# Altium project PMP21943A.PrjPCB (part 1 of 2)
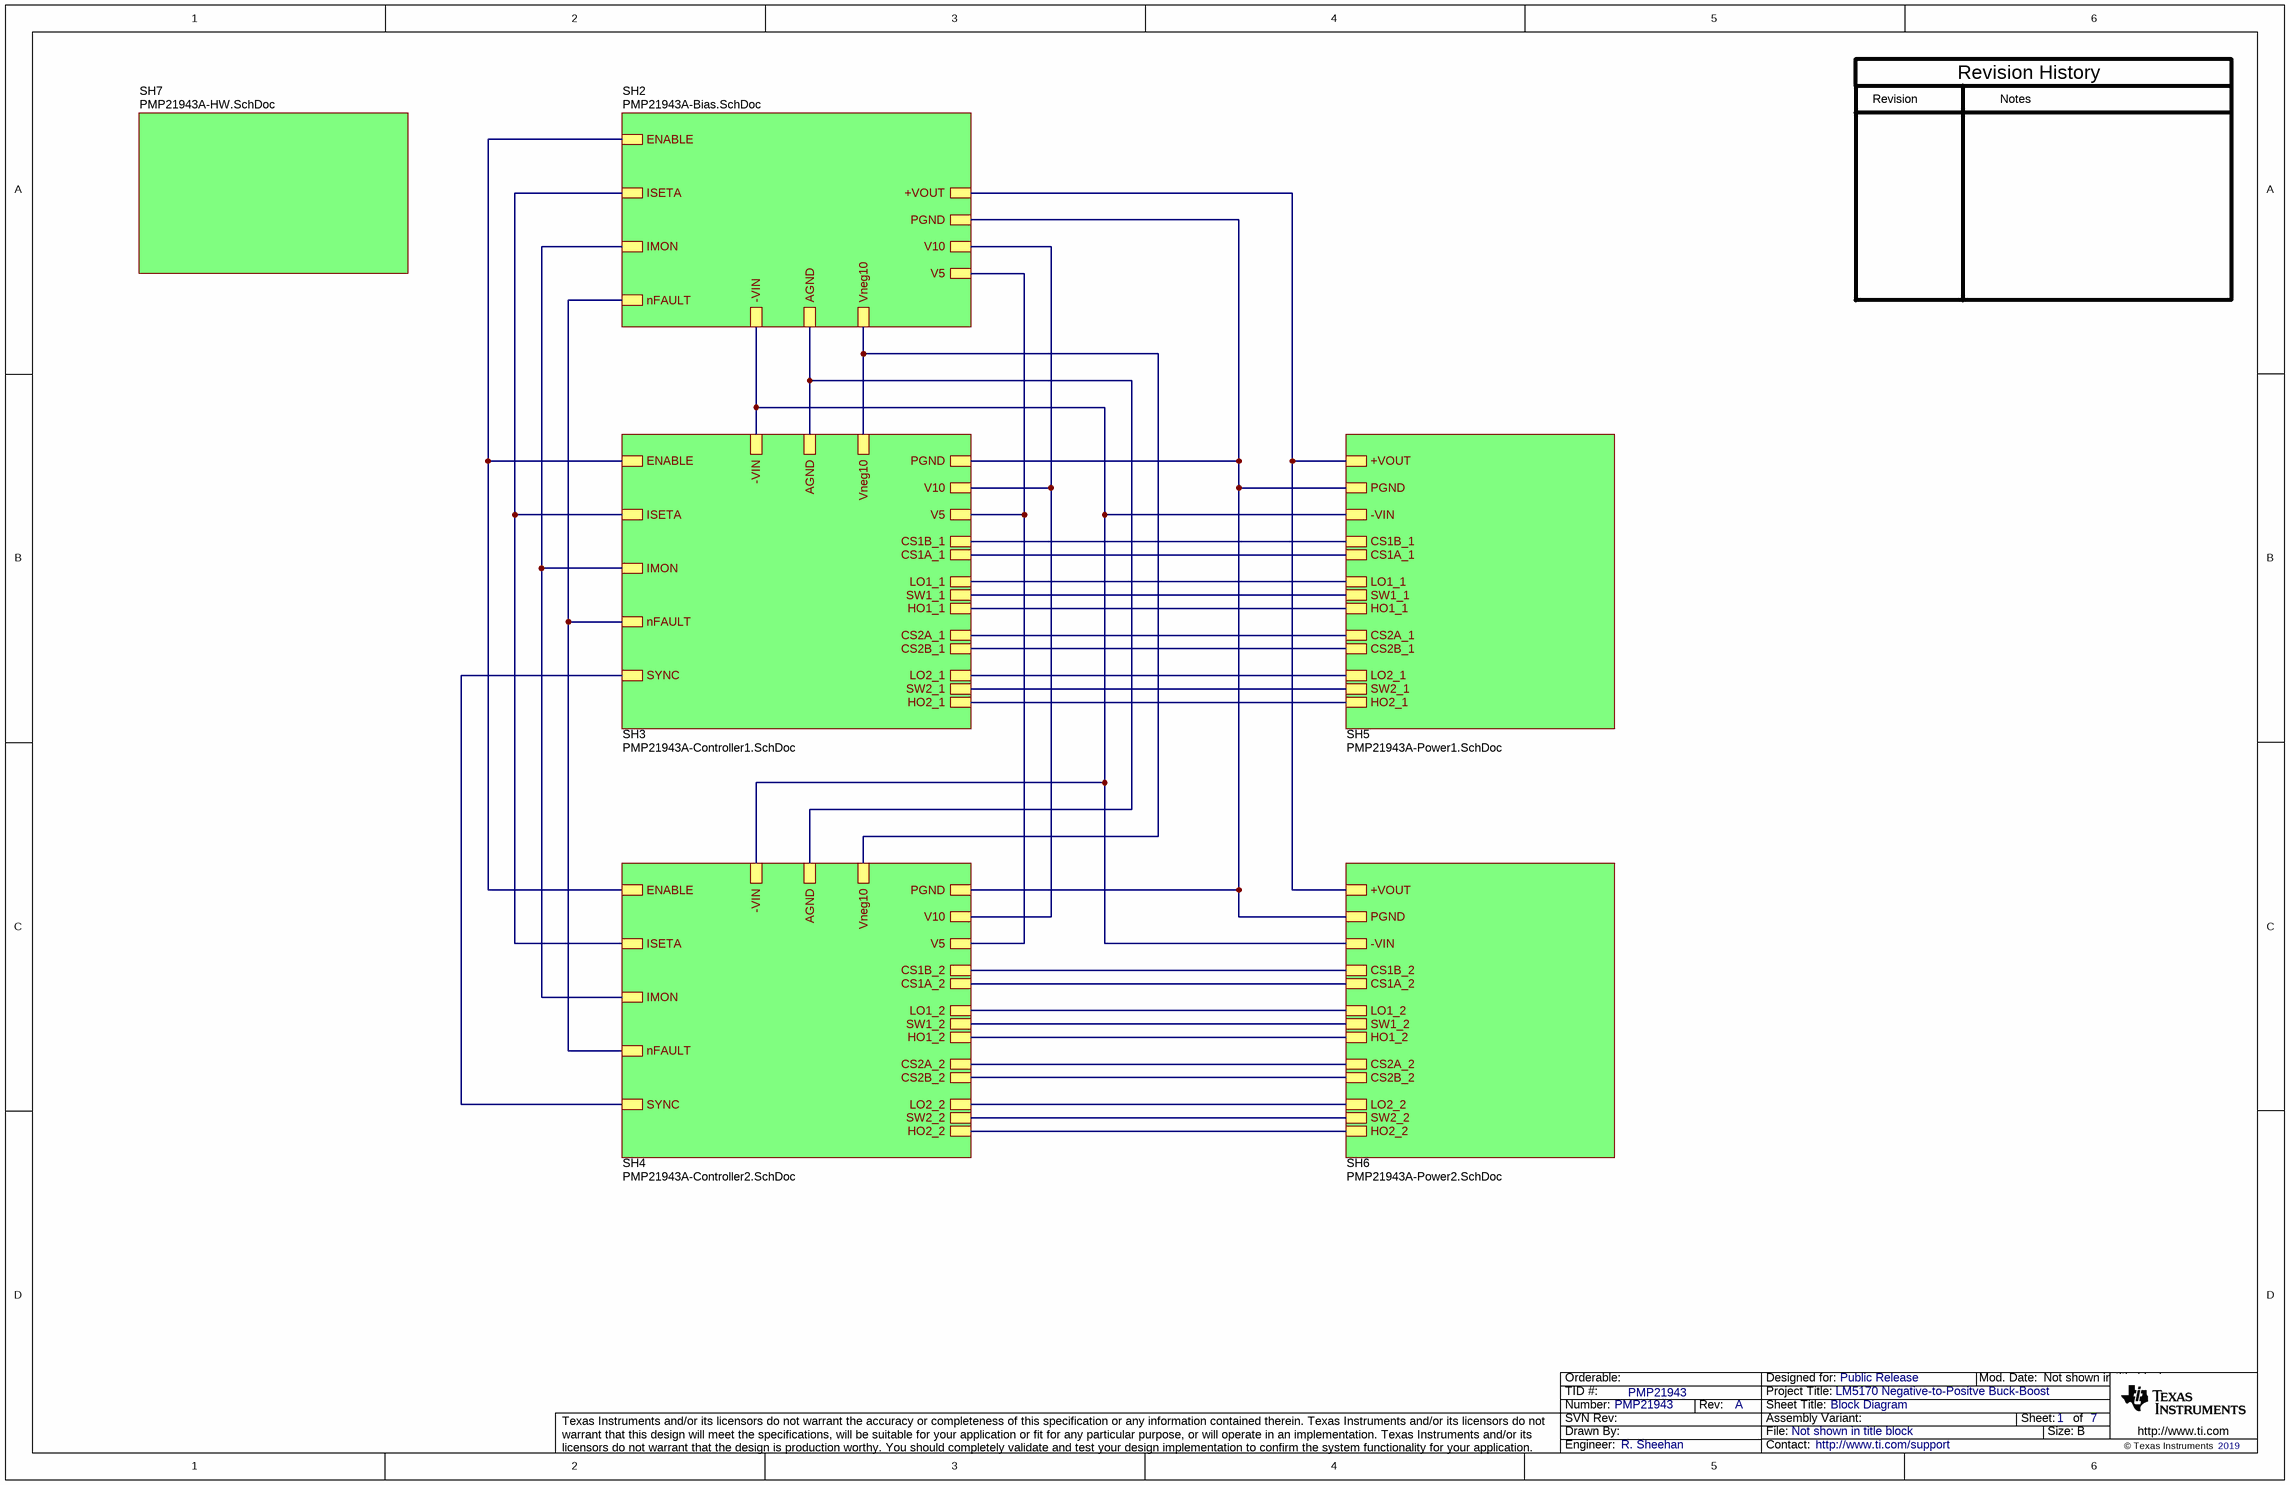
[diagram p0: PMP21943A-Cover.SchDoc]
CopyrightYear: 2019; PCB_Layout: R. Sheehan; PCB_Rev: A; PRJ_Customer: Public Release; PRJ_Engineer: R. Sheehan; PRJ_Number: PMP21943; PRJ_Title: LM5170 Negative-to-Positve Buck-Boost; SCH_Rev: A; TechSupport: http://www.ti.com/support; TID: PMP21943
7 sheets, 368 parts. Net scope: hierarchical (ports join the sheet entries above them; power ports are global).
Board file: PMP21943A.PcbDoc
Sheets:
  PMP21943A-Cover.SchDoc
    SH3 = PMP21943A-Controller1.SchDoc
    SH5 = PMP21943A-Power1.SchDoc
    SH7 = PMP21943A-HW.SchDoc
    SH2 = PMP21943A-Bias.SchDoc
    SH4 = PMP21943A-Controller2.SchDoc
    SH6 = PMP21943A-Power2.SchDoc

## Sheet PMP21943A-Cover.SchDoc: Block Diagram
size 431 x 279 mm; Date: Not shown in title block; ApprovedBy: Not shown in title block; CheckedBy: Not shown in title block; Author: Not shown in title block; CompanyName: Not shown in title block; Engineer: Not shown in title block; Organization: Not shown in title block; Address1: Not shown in title block; Address2: Not shown in title block; Address3: Not shown in title block; Address4: Not shown in title block; DocumentNumber: 1; Revision: Use project parameter SCH_Rev; SheetNumber: 1; SheetTotal: 7; PageSetup: Record=PageOptions¦CenterHorizontal=True¦CenterVertical=True¦PrintScale=1.00¦XCorrection=1.00¦YCorrection=1.00¦PrintKind=0¦BorderSize=5000000¦LeftOffset=0¦BottomOffset=0¦Orientation=2¦PaperLength=1000¦PaperWidth=1000¦Scale=100¦PaperSource=15¦PrintQuality=600¦MediaType=1¦DitherType=10¦PaperKind=Letter¦PrintScaleMode=1

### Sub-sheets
SH2 = PMP21943A-Bias.SchDoc: +VOUT, PGND, V5, ENABLE, ISETA, AGND, V10, -VIN, IMON, nFAULT, Vneg10
SH3 = PMP21943A-Controller1.SchDoc: ISETA, CS1A_1, CS1B_1, SW1_1, HO1_1, LO1_1, HO2_1, CS2A_1, CS2B_1, SW2_1, LO2_1, nFAULT, ENABLE, V10, AGND, -VIN, V5, SYNC, IMON, Vneg10, PGND
SH4 = PMP21943A-Controller2.SchDoc: ISETA, CS1A_2, CS1B_2, SW1_2, HO1_2, LO1_2, HO2_2, CS2A_2, CS2B_2, SW2_2, LO2_2, nFAULT, ENABLE, V10, AGND, -VIN, V5, SYNC, IMON, Vneg10, PGND
SH5 = PMP21943A-Power1.SchDoc: CS1B_1, CS1A_1, LO1_1, HO1_1, SW1_1, CS2A_1, CS2B_1, LO2_1, HO2_1, SW2_1, PGND, +VOUT, -VIN
SH6 = PMP21943A-Power2.SchDoc: CS1B_2, CS1A_2, LO1_2, HO1_2, SW1_2, CS2A_2, CS2B_2, LO2_2, HO2_2, SW2_2, PGND, +VOUT, -VIN
SH7 = PMP21943A-HW.SchDoc: no entries

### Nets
+VOUT: sheet SH5/+VOUT, sheet SH2/+VOUT, sheet SH6/+VOUT
-VIN: sheet SH3/-VIN, sheet SH5/-VIN, sheet SH2/-VIN, sheet SH4/-VIN, sheet SH6/-VIN
AGND: sheet SH3/AGND, sheet SH2/AGND, sheet SH4/AGND
PGND: sheet SH3/PGND, sheet SH5/PGND, sheet SH2/PGND, sheet SH4/PGND, sheet SH6/PGND
V5: sheet SH3/V5, sheet SH2/V5, sheet SH4/V5
V10: sheet SH3/V10, sheet SH2/V10, sheet SH4/V10
CS1A_1: sheet SH3/CS1A_1, sheet SH5/CS1A_1
CS1A_2: sheet SH4/CS1A_2, sheet SH6/CS1A_2
CS1B_1: sheet SH3/CS1B_1, sheet SH5/CS1B_1
CS1B_2: sheet SH4/CS1B_2, sheet SH6/CS1B_2
CS2A_1: sheet SH3/CS2A_1, sheet SH5/CS2A_1
CS2A_2: sheet SH4/CS2A_2, sheet SH6/CS2A_2
CS2B_1: sheet SH3/CS2B_1, sheet SH5/CS2B_1
CS2B_2: sheet SH4/CS2B_2, sheet SH6/CS2B_2
ENABLE: sheet SH3/ENABLE, sheet SH2/ENABLE, sheet SH4/ENABLE
HO1_1: sheet SH3/HO1_1, sheet SH5/HO1_1
HO1_2: sheet SH4/HO1_2, sheet SH6/HO1_2
HO2_1: sheet SH3/HO2_1, sheet SH5/HO2_1
HO2_2: sheet SH4/HO2_2, sheet SH6/HO2_2
IMON: sheet SH3/IMON, sheet SH2/IMON, sheet SH4/IMON
ISETA: sheet SH3/ISETA, sheet SH2/ISETA, sheet SH4/ISETA
LO1_1: sheet SH3/LO1_1, sheet SH5/LO1_1
LO1_2: sheet SH4/LO1_2, sheet SH6/LO1_2
LO2_1: sheet SH3/LO2_1, sheet SH5/LO2_1
LO2_2: sheet SH4/LO2_2, sheet SH6/LO2_2
nFAULT: sheet SH3/nFAULT, sheet SH2/nFAULT, sheet SH4/nFAULT
SW1_1: sheet SH3/SW1_1, sheet SH5/SW1_1
SW1_2: sheet SH4/SW1_2, sheet SH6/SW1_2
SW2_1: sheet SH3/SW2_1, sheet SH5/SW2_1
SW2_2: sheet SH4/SW2_2, sheet SH6/SW2_2
SYNC: sheet SH3/SYNC, sheet SH4/SYNC
Vneg10: sheet SH3/Vneg10, sheet SH2/Vneg10, sheet SH4/Vneg10

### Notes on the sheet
- Revision
- Notes
- Revision History

## Sheet PMP21943A-Controller1.SchDoc: Controller
size 431 x 279 mm; Date: Not shown in title block; ApprovedBy: Not shown in title block; CheckedBy: Not shown in title block; Author: Not shown in title block; CompanyName: Not shown in title block; Engineer: Not shown in title block; Organization: Not shown in title block; Address1: Not shown in title block; Address2: Not shown in title block; Address3: Not shown in title block; Address4: Not shown in title block; DocumentNumber: 3; Revision: Use project parameter SCH_Rev; SheetNumber: 3; SheetTotal: 7; PageSetup: Record=PageOptions¦CenterHorizontal=True¦CenterVertical=True¦PrintScale=1.00¦XCorrection=1.00¦YCorrection=1.00¦PrintKind=0¦BorderSize=5000000¦LeftOffset=0¦BottomOffset=0¦Orientation=2¦PaperLength=1000¦PaperWidth=1000¦Scale=100¦PaperSource=15¦PrintQuality=600¦MediaType=1¦DitherType=10¦PaperKind=Letter¦PrintScaleMode=1
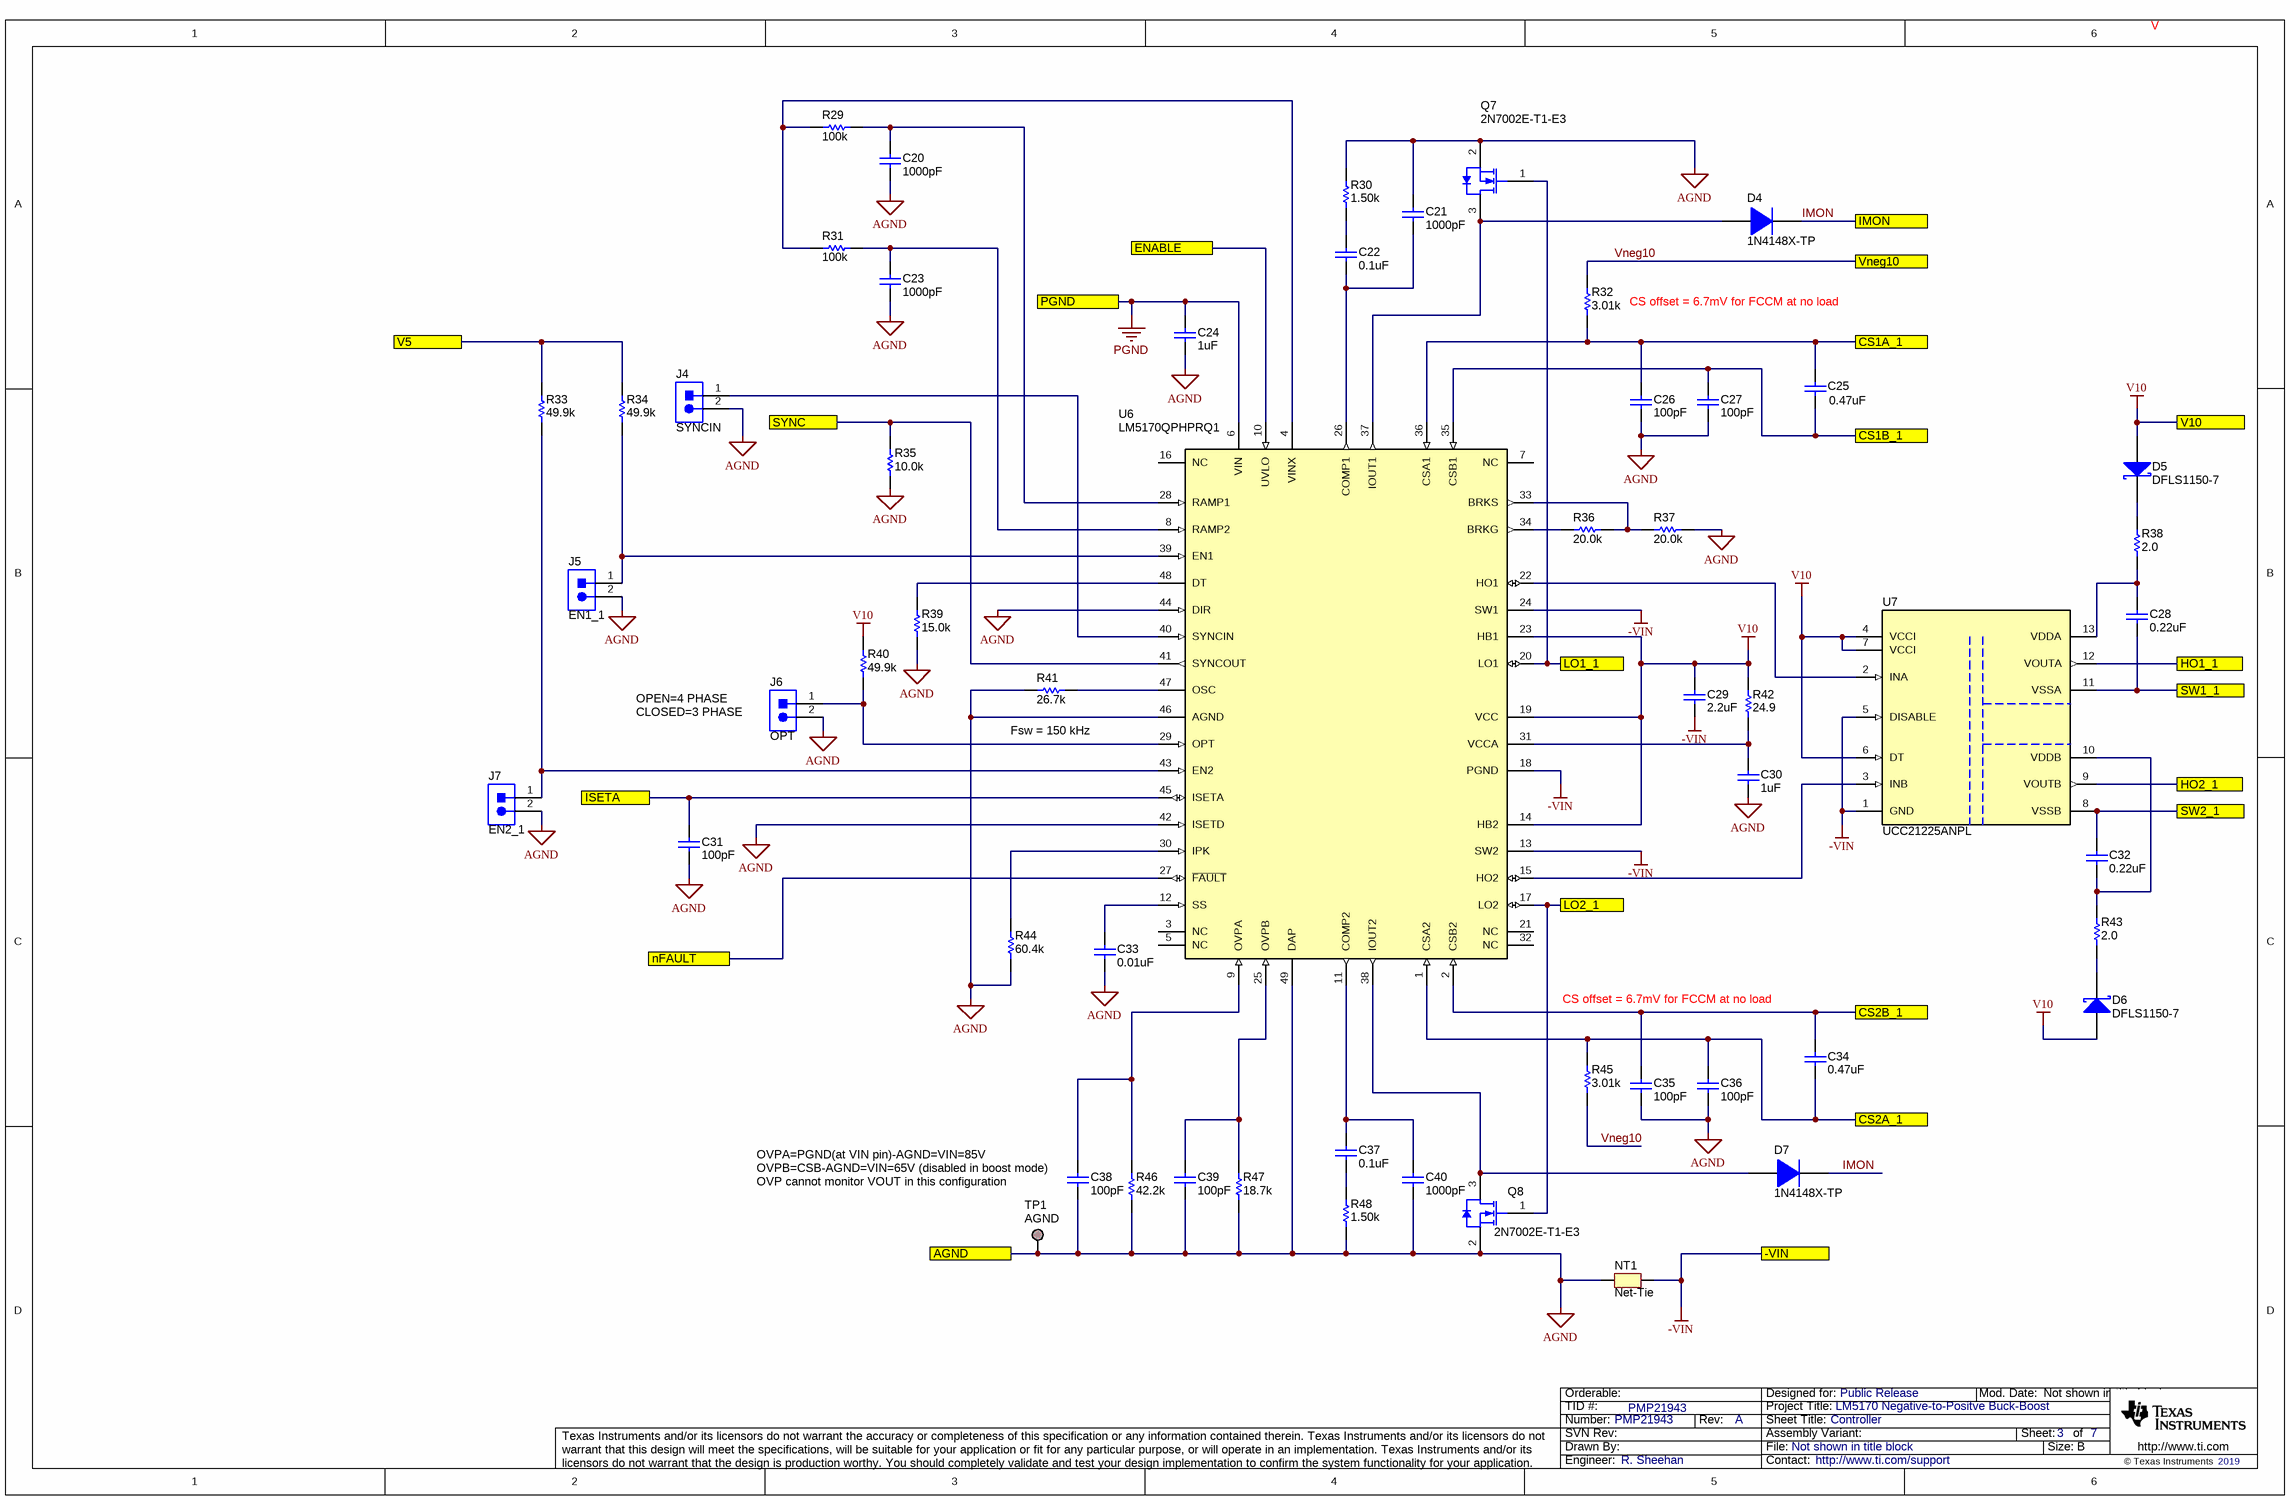
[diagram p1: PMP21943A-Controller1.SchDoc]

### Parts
C20  ValueDisplayed: 1000pF  [0603L]  (hidden comment: Capacitor)
C21  ValueDisplayed: 1000pF  [0603L]  (hidden comment: GRM188R72A102KA01D)
C22  ValueDisplayed: 0.1uF  [0603L]  (hidden comment: GRM188R72A104KA35D)
C23  ValueDisplayed: 1000pF  [0603L]  (hidden comment: Capacitor)
C24  ValueDisplayed: 1uF  [0805_HV]  (hidden comment: Capacitor)
C25  ValueDisplayed: 0.47uF  [0603]  (hidden comment: GRM188R71C474KA88D)
C26  ValueDisplayed: 100pF  [0603L]  (hidden comment: Capacitor)
C27  ValueDisplayed: 100pF  [0603L]  (hidden comment: Capacitor)
C28  ValueDisplayed: 0.22uF  [0603L]  (hidden comment: Capacitor)
C29  ValueDisplayed: 2.2uF  [0805_HV]  (hidden comment: Capacitor)
C30  ValueDisplayed: 1uF  [0603L]  (hidden comment: Capacitor)
C31  ValueDisplayed: 100pF  [0603L]  (hidden comment: Capacitor)
C32  ValueDisplayed: 0.22uF  [0603L]  (hidden comment: Capacitor)
C33  ValueDisplayed: 0.01uF  [0603L]  (hidden comment: Capacitor)
C34  ValueDisplayed: 0.47uF  [0603L]  (hidden comment: GRM188R71C474KA88D)
C35  ValueDisplayed: 100pF  [0603L]  (hidden comment: Capacitor)
C36  ValueDisplayed: 100pF  [0603L]  (hidden comment: Capacitor)
C37  ValueDisplayed: 0.1uF  [0603L]  (hidden comment: GRM188R72A104KA35D)
C38  ValueDisplayed: 100pF  [0603L]  (hidden comment: Capacitor)
C39  ValueDisplayed: 100pF  [0603L]  (hidden comment: Capacitor)
C40  ValueDisplayed: 1000pF  [0603L]  (hidden comment: GRM188R72A102KA01D)
D4  1N4148X-TP  [SOD-523]
D5  DFLS1150-7  [PowerDI123]
D6  DFLS1150-7  [PowerDI123]
D7  1N4148X-TP  [SOD-523]
J4  SYNCIN  [Samtec_HTSW-102-07-G-S]
J5  EN1_1  [Samtec_HTSW-102-07-G-S]
J6  OPT  [Samtec_HTSW-102-07-G-S]
J7  EN2_1  [Samtec_HTSW-102-07-G-S]
NT1  Net-Tie  [Net-Tie_10mil]  (net tie, no BOM)
Q7  2N7002E-T1-E3  [SOT-23]
Q8  2N7002E-T1-E3  [SOT-23]
R29  ValueDisplayed: 100k  [0603L]  (hidden comment: Resistor)
R30  ValueDisplayed: 1.50k  [0603L]  (hidden comment: CRCW06031K50FKEA)
R31  ValueDisplayed: 100k  [0603L]  (hidden comment: Resistor)
R32  ValueDisplayed: 3.01k  [0603]  (hidden comment: CRCW06033K01FKEA)
R33  ValueDisplayed: 49.9k  [0603L]  (hidden comment: Resistor)
R34  ValueDisplayed: 49.9k  [0603L]  (hidden comment: Resistor)
R35  ValueDisplayed: 10.0k  [0603L]  (hidden comment: Resistor)
R36  ValueDisplayed: 20.0k  [0603L]  (hidden comment: Resistor)
R37  ValueDisplayed: 20.0k  [0603L]  (hidden comment: Resistor)
R38  ValueDisplayed: 2.0  [0603L]  (hidden comment: Resistor)
R39  ValueDisplayed: 15.0k  [0603L]  (hidden comment: Resistor)
R40  ValueDisplayed: 49.9k  [0603L]  (hidden comment: Resistor)
R41  ValueDisplayed: 26.7k  [0603L]  (hidden comment: Resistor)
R42  ValueDisplayed: 24.9  [0603L]  (hidden comment: CRCW060324R9FKEA)
R43  ValueDisplayed: 2.0  [0603L]  (hidden comment: Resistor)
R44  ValueDisplayed: 60.4k  [0603]  (hidden comment: CRCW060360K4FKEA)
R45  ValueDisplayed: 3.01k  [0603]  (hidden comment: CRCW06033K01FKEA)
R46  ValueDisplayed: 42.2k  [0603L]  (hidden comment: Resistor)
R47  ValueDisplayed: 18.7k  [0603L]  (hidden comment: Resistor)
R48  ValueDisplayed: 1.50k  [0603L]  (hidden comment: CRCW06031K50FKEA)
TP1  AGND  [Keystone1598-2]
U6  PartNumber: LM5170QPHPRQ1  [PHP0048D_L]  (hidden comment: CMP-0013575-3)
U7  UCC21225ANPL  [NPL0013A]

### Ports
-VIN, AGND, CS1A_1, CS1B_1, CS2A_1, CS2B_1, ENABLE, HO1_1, HO2_1, IMON, ISETA, LO1_1, LO2_1, nFAULT, PGND, SW1_1, SW2_1, SYNC, V5, V10, Vneg10

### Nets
-VIN: C29.2 NT1.2 U6.13(SW2) U6.18(PGND) U6.24(SW1) U7.1(GND) U7.5(DISABLE) ; port -VIN
AGND: C20.2 C21.1 C23.2 C24.2 C26.2 C27.2 C30.2 C31.2 C33.2 C35.2 C36.2 C38.2 C39.2 C40.2 J4.2 J5.2 J6.2 J7.2 NT1.1 Q7.2(S) Q8.2(S) R30.2 R35.2 R37.1 R39.1 R41.1 R44.1 R46.1 R47.1 R48.1 TP1.1 U6.42(ISETD) U6.44(DIR) U6.46(AGND) U6.49(DAP) ; port AGND
PGND: C24.1 U6.6(VIN) ; port PGND
V5: R33.2 R34.2 ; port V5
V10: C29.1 D5.2(A) D6.2(A) R40.2 R42.2 U6.14(HB2) U6.19(VCC) U6.23(HB1) U7.4(VCCI) U7.6(DT) U7.7(VCCI) ; port V10
CS1A_1: C25.1 C26.1 R32.1 U6.36(CSA1) ; port CS1A_1
CS1B_1: C25.2 C27.1 U6.35(CSB1) ; port CS1B_1
CS2A_1: C34.2 C36.1 R45.2 U6.1(CSA2) ; port CS2A_1
CS2B_1: C34.1 C35.1 U6.2(CSB2) ; port CS2B_1
ENABLE: U6.10(UVLO) ; port ENABLE
HO1_1: U7.12(VOUTA) ; port HO1_1
HO2_1: U7.9(VOUTB) ; port HO2_1
IMON: D4.1(K) D7.1(K) ; port IMON
ISETA: C31.1 U6.45(ISETA) ; port ISETA
LO1_1: Q7.1(G) U6.20(LO1) ; port LO1_1
LO2_1: Q8.1(G) U6.17(LO2) ; port LO2_1
nFAULT: U6.27(~{FAULT}) ; port nFAULT
SW1_1: C28.1 U7.11(VSSA) ; port SW1_1
SW2_1: C32.2 U7.8(VSSB) ; port SW2_1
SYNC: R35.1 U6.41(SYNCOUT) ; port SYNC
Vneg10: R32.2 R45.1 ; port Vneg10
NetC20_1: C20.1 R29.2 U6.28(RAMP1)
NetC21_2: C21.2 C22.2 U6.26(COMP1)
NetC22_1: C22.1 R30.1
NetC23_1: C23.1 R31.2 U6.8(RAMP2)
NetC28_2: C28.2 R38.1 U7.13(VDDA)
NetC30_1: C30.1 R42.1 U6.31(VCCA)
NetC32_1: C32.1 R43.1 U7.10(VDDB)
NetC33_1: C33.1 U6.12(SS)
NetC37_1: C37.1 C40.1 U6.11(COMP2)
NetC37_2: C37.2 R48.2
NetC38_1: C38.1 R46.2 U6.9(OVPA)
NetC39_1: C39.1 R47.2 U6.25(OVPB)
NetD4_2: D4.2(A) Q7.3(D) U6.37(IOUT1)
NetD5_1: D5.1(K) R38.2
NetD6_1: D6.1(K) R43.2
NetD7_2: D7.2(A) Q8.3(D) U6.38(IOUT2)
NetJ4_1: J4.1 U6.40(SYNCIN)
NetJ5_1: J5.1 R34.1 U6.39(EN1)
NetJ6_1: J6.1 R40.1 U6.29(OPT)
NetJ7_1: J7.1 R33.1 U6.43(EN2)
NetR29_1: R29.1 R31.1 U6.4(VINX)
NetR36_1: R36.1 R37.2 U6.33(BRKS)
NetR36_2: R36.2 U6.34(BRKG)
NetR39_2: R39.2 U6.48(DT)
NetR41_2: R41.2 U6.47(OSC)
NetR44_2: R44.2 U6.30(IPK)
NetU6_15: U6.15(HO2) U7.3(INB)
NetU6_22: U6.22(HO1) U7.2(INA)

Not connected (* = marked no-connect by the designer): U6 3(NC) 5(NC) 7(NC) 16(NC) 21(NC) 32(NC)

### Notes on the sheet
- (near R32) CS offset = 6.7mV for FCCM at no load
- (near J6) OPEN=4 PHASE
  CLOSED=3 PHASE
- (near R41) Fsw = 150 kHz
- CS offset = 6.7mV for FCCM at no load
- (near C38) OVPA=PGND(at VIN pin)-AGND=VIN=85V
  OVPB=CSB-AGND=VIN=65V (disabled in boost mode)
  OVP cannot monitor VOUT in this configuration

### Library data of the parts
C20 C23 = CMP-0006993-4: CAP, CERM, 1000 pF, 100 V, +/- 5%, C0G/NP0, 0603; PartNumber: C1608C0G2A102J080AA; Manufacturer: TDK; Polarized: N; Value: 1000pF; U/M: EA; Cap_F: 1nF; ESR_ohm: 0.0589; Value1: 0.0589 ohm; VDC_V: 100V; TaMin_C: -55°C; TaMax_C: 125°C; Cap_Case: 0603; AEC Category: Q200; SizeArea_mm2: 1.28; SizeAreaWB_mm2: 4.68; SizeX_mm: 1.6; SizeY_mm: 0.8; SizeZ_mm: 1
C21 C40 = CMP-0007467-4: CAP, CERM, 1000 pF, 100 V, +/- 10%, X7R, 0603; Manufacturer: MuRata; Polarized: N; Value: 1000pF; U/M: EA; Cap_F: 1nF; Value1: Unknown; VDC_V: 100V; TaMin_C: -55°C; TaMax_C: 125°C; Cap_Case: 0603; AEC Category: Q200; SizeArea_mm2: 1.28; SizeAreaWB_mm2: 4.68; SizeX_mm: 1.6; SizeY_mm: 0.8; SizeZ_mm: 1
C22 C37 = CMP-0007469-4: CAP, CERM, 0.1 uF, 100 V, +/- 10%, X7R, 0603; Manufacturer: MuRata; Polarized: N; Value: 0.1uF; U/M: EA; Cap_F: 100nF; Value1: Unknown; VDC_V: 100V; TaMin_C: -55°C; TaMax_C: 125°C; Cap_Case: 0603; SizeArea_mm2: 1.28; SizeAreaWB_mm2: 4.68; SizeX_mm: 1.6; SizeY_mm: 0.8; SizeZ_mm: 1; AEC Category: Q200
C24 = CMP-0007891-2: CAP, CERM, 1 uF, 100 V, +/- 10%, X7S, 0805; PartNumber: C2012X7S2A105K125AB; Manufacturer: TDK; Polarized: N; Value: 1uF; U/M: EA; Cap_F: 1µF; ESR_ohm: 8.255m; Value1: 0.008255 ohm; VDC_V: 100V; IRMS_A: 2.27442A; TaMin_C: -55°C; TaMax_C: 125°C; Cap_Case: 0805; AEC Category: Q200; SizeArea_mm2: 2.5; SizeAreaWB_mm2: 6.75; SizeX_mm: 2; SizeY_mm: 1.25; SizeZ_mm: 1.45
C25 = CMP-0007398-4: CAP, CERM, 0.47 uF, 16 V, +/- 10%, X7R, 0603; Manufacturer: MuRata; Polarized: N; Value: 0.47uF; U/M: EA; Cap_F: 470nF; Value1: Unknown; VDC_V: 16V; TaMin_C: -55°C; TaMax_C: 125°C; AEC Category: Q200; SizeArea_mm2: 1.28; SizeAreaWB_mm2: 4.68; SizeX_mm: 1.6; SizeY_mm: 0.8; SizeZ_mm: 1
C26 C27 C31 C35 C36 C38 C39 = CMP-0006841-4: CAP, CERM, 100 pF, 50 V, +/- 5%, C0G/NP0, 0603; PartNumber: C0603C101J5GACTU; Manufacturer: Kemet; Polarized: N; Value: 100pF; U/M: EA; Value1: Unknown; VDC_V: 50V; TaMin_C: -55°C; TaMax_C: 125°C; Cap_Case: 0603; AEC Category: Q200; SizeArea_mm2: 1.28; SizeAreaWB_mm2: 4.68; SizeX_mm: 1.6; SizeY_mm: 0.8; SizeZ_mm: 1
C28 C32 = CMP-0007047-4: CAP, CERM, 0.22 uF, 50 V, +/- 10%, X7R, 0603; PartNumber: C1608X7R1H224K080AB; Manufacturer: TDK; Polarized: N; Value: 0.22uF; U/M: EA; Cap_F: 220nF; ESR_ohm: 0.021699; Value1: 0.021699 ohm; VDC_V: 50V; IRMS_A: 1.12496A; TaMin_C: -55°C; TaMax_C: 125°C; Cap_Case: 0603; SizeArea_mm2: 1.28; SizeAreaWB_mm2: 4.68; SizeX_mm: 1.6; SizeY_mm: 0.8; SizeZ_mm: 1; AEC Category: Q200
C29 = CMP-0007867-2: CAP, CERM, 2.2 uF, 16 V, +/- 10%, X7R, 0805; PartNumber: C2012X7R1C225K125AB; Manufacturer: TDK; Value: 2.2uF; U/M: EA; VDC_V: 16V; Polarized: N; Cap_F: 2.2µF; ESR_ohm: 4.9m; Value1: 0.0049 ohm; TaMin_C: -55°C; TaMax_C: 125°C; Cap_Case: 0805; AEC Category: Q200; SizeArea_mm2: 2.5; SizeAreaWB_mm2: 6.75; SizeX_mm: 2; SizeY_mm: 1.25; SizeZ_mm: 1.45
C30 = CMP-0007405-4: CAP, CERM, 1 uF, 25 V, +/- 10%, X7R, 0603; PartNumber: GRM188R71E105KA12D; Manufacturer: MuRata; Polarized: N; Value: 1uF; U/M: EA; Cap_F: 1µF; Value1: Unknown; VDC_V: 25V; TaMin_C: -55°C; TaMax_C: 125°C; Cap_Case: 0603; AEC Category: Q200; SizeArea_mm2: 1.28; SizeAreaWB_mm2: 4.68; SizeX_mm: 1.6; SizeY_mm: 0.8; SizeZ_mm: 1
C33 = CMP-0006727-4: CAP, CERM, 0.01 uF, 100 V, +/- 10%, X7R, 0603; PartNumber: 06031C103KAT2A; Manufacturer: AVX; Polarized: N; Value: 0.01uF; U/M: EA; Cap_F: 10nF; ESR_ohm: 0.098; Value1: 0.098 ohm; VDC_V: 100V; TaMin_C: -55°C; TaMax_C: 125°C; Cap_Case: 0603; SizeArea_mm2: 1.28; SizeAreaWB_mm2: 4.68; SizeX_mm: 1.6; SizeY_mm: 0.8; SizeZ_mm: 1; AEC Category: Q200
C34 = CMP-0007398-4: CAP, CERM, 0.47 uF, 16 V, +/- 10%, X7R, 0603; Manufacturer: MuRata; Polarized: N; Value: 0.47uF; U/M: EA; Cap_F: 470nF; Value1: Unknown; VDC_V: 16V; TaMin_C: -55°C; TaMax_C: 125°C; Cap_Case: 0603; AEC Category: Q200; SizeArea_mm2: 1.28; SizeAreaWB_mm2: 4.68; SizeX_mm: 1.6; SizeY_mm: 0.8; SizeZ_mm: 1
D4 D7 = CMP-0076957-3: Diode, Switching, 75 V, 0.3 A, SOD-523; Manufacturer: Micro Commercial Components; Vf_V: 1.25V; Value: 75V; Value1: 0.3A; Io_A: 300mA; TJmax_C: 150°C; AEC Category: Q101; Green_Lifecycle: Not Set; Green_REACh: Incomplete; SizeArea_mm2: 1.53; SizeAreaWB_mm2: 5.13; SizeX_mm: 1.7; SizeY_mm: 0.9; SizeZ_mm: 0.65
D5 D6 = CMP-0077034-2: Diode, Schottky, 150 V, 1 A, PowerDI123; Manufacturer: Diodes Inc.; Vf_V: 820mV; Value: 150V; Value1: 1A; Value2: 0.82V; TJmax_C: 175°C; SizeAreaWB_mm2: 13.066; SizeArea_mm2: 6.586; SizeX_mm: 3.7; SizeY_mm: 1.78; SizeZ_mm: 0.98; AEC Category: Q101; Green_Lifecycle: Active; Green_REACh: Passed
J4-J7 = CMP-0075483-1: Header, 100mil, 2x1, Gold, TH; PartNumber: HTSW-102-07-G-S; Manufacturer: Samtec; CNHeader: True; CT: False; Green_Lifecycle: Active; Green_REACh: Passed
NT1 = CMP-0078142-3: Single point connection between nets.
Q7 Q8 = CMP-0000771-1: MOSFET, N-CH, 60 V, 0.24 A, SOT-23; Manufacturer: Vishay-Siliconix; Alternate Manufacturer: None; U/M: EA; ChType: N; Value: 60V; Value1: 1; Rdson45_ohm: 1.8; Value2: 0.4 nC; QgTyp_nC: 0.4; Vgs_V: 20V; IdsMax_A: 2.4dA; AEC Category: Q101; SizeArea_mm2: 7.5; SizeAreaWB_mm2: 14; SizeX_mm: 2.5; SizeY_mm: 3; SizeZ_mm: 1.1
R29 R31 = CMP-0021990-4: RES, 100 k, 1%, 0.1 W, AEC-Q200 Grade 0, 0603; PartNumber: CRCW0603100KFKEA; Manufacturer: Vishay-Dale; Value: 100k; Power_W: 100mW; Value2: 0.1W; VDC_V: 75V; TempCo: 100 ppm/C; EIA_Code: E96; SizeArea_mm2: 1.28; SizeX_mm: 1.6; SizeY_mm: 0.8; SizeZ_mm: 1; AEC Category: Q200; AEC Qualified: Y; AEC Grade: 0
R30 R48 = CMP-0022126-4: RES, 1.50 k, 1%, 0.1 W, AEC-Q200 Grade 0, 0603; Manufacturer: Vishay-Dale; Value: 1.50k; Res_ohm: 1.5k; Value_Code: 1k50; Power_W: 100mW; Value2: 0.1W; VDC_V: 75V; TempCo: 100 ppm/C; EIA_Code: E96; SizeArea_mm2: 1.28; SizeX_mm: 1.6; SizeY_mm: 0.8; SizeZ_mm: 1; AEC Category: Q200; AEC Qualified: Y; AEC Grade: 0
R32 R45 = CMP-0022371-4: RES, 3.01 k, 1%, 0.1 W, AEC-Q200 Grade 0, 0603; Manufacturer: Vishay-Dale; Power_W: 100mW; TempCo: 100 ppm/C; Value_Code: 3k01; Value: 3.01k; EIA_Code: E96; SizeX_mm: 1.6; SizeY_mm: 0.8; SizeZ_mm: 1; Value2: 0.1W; SizeArea_mm2: 1.28; AEC Qualified: Y; VDC_V: 75V; AEC Category: Q200; AEC Grade: 0
R33 R34 R40 = CMP-0022447-4: RES, 49.9 k, 1%, 0.1 W, AEC-Q200 Grade 0, 0603; PartNumber: CRCW060349K9FKEA; Manufacturer: Vishay-Dale; Value: 49.9k; Value_Code: 49k9; Power_W: 100mW; Value2: 0.1W; VDC_V: 75V; TempCo: 100 ppm/C; EIA_Code: E96; AEC Category: Q200; AEC Grade: 0; AEC Qualified: Y; SizeArea_mm2: 1.28; SizeX_mm: 1.6; SizeY_mm: 0.8; SizeZ_mm: 1
R35 = CMP-0021998-4: RES, 10.0 k, 1%, 0.1 W, AEC-Q200 Grade 0, 0603; PartNumber: CRCW060310K0FKEA; Manufacturer: Vishay-Dale; Value: 10.0k; Res_ohm: 10k; Value_Code: 10k0; Power_W: 100mW; Value2: 0.1W; VDC_V: 75V; TempCo: 100 ppm/C; EIA_Code: E96; AEC Category: Q200; AEC Grade: 0; AEC Qualified: Y; SizeArea_mm2: 1.28; SizeX_mm: 1.6; SizeY_mm: 0.8; SizeZ_mm: 1
R36 R37 = CMP-0022204-4: RES, 20.0 k, 1%, 0.1 W, AEC-Q200 Grade 0, 0603; PartNumber: CRCW060320K0FKEA; Manufacturer: Vishay-Dale; Value: 20.0k; Res_ohm: 20k; Value_Code: 20k0; Power_W: 100mW; Value2: 0.1W; VDC_V: 75V; TempCo: 100 ppm/C; EIA_Code: E96; SizeArea_mm2: 1.28; SizeX_mm: 1.6; SizeY_mm: 0.8; SizeZ_mm: 1; AEC Category: Q200; AEC Qualified: Y; AEC Grade: 0
R38 R43 = CMP-0025776-4: RES, 2.0, 5%, 0.1 W, AEC-Q200 Grade 0, 0603; PartNumber: CRCW06032R00JNEA; Manufacturer: Vishay-Dale; Value: 2.0; Res_ohm: 2; Value_Code: 2R00; Power_W: 100mW; Value2: 0.1W; VDC_V: 75V; TempCo: 200 ppm/C; EIA_Code: E24; AEC Category: Q200; AEC Qualified: Y; AEC Grade: 0; SizeArea_mm2: 1.28; SizeX_mm: 1.6; SizeY_mm: 0.8; SizeZ_mm: 1
R39 = CMP-0022066-4: RES, 15.0 k, 1%, 0.1 W, AEC-Q200 Grade 0, 0603; PartNumber: CRCW060315K0FKEA; Manufacturer: Vishay-Dale; Value: 15.0k; Res_ohm: 15k; Value_Code: 15k0; Power_W: 100mW; Value2: 0.1W; VDC_V: 75V; TempCo: 100 ppm/C; EIA_Code: E96; SizeArea_mm2: 1.28; SizeX_mm: 1.6; SizeY_mm: 0.8; SizeZ_mm: 1; AEC Category: Q200; AEC Qualified: Y; AEC Grade: 0
R41 = CMP-0022249-4: RES, 26.7 k, 1%, 0.1 W, AEC-Q200 Grade 0, 0603; PartNumber: CRCW060326K7FKEA; Manufacturer: Vishay-Dale; Value: 26.7k; Value_Code: 26k7; Power_W: 100mW; Value2: 0.1W; VDC_V: 75V; TempCo: 100 ppm/C; EIA_Code: E96; SizeArea_mm2: 1.28; SizeX_mm: 1.6; SizeY_mm: 0.8; SizeZ_mm: 1; AEC Category: Q200; AEC Qualified: Y; AEC Grade: 0
R42 = CMP-0022239-4: RES, 24.9, 1%, 0.1 W, AEC-Q200 Grade 0, 0603; Manufacturer: Vishay-Dale; Value: 24.9; Value_Code: 24R9; Power_W: 100mW; Value2: 0.1W; VDC_V: 75V; TempCo: 100 ppm/C; EIA_Code: E96; AEC Category: Q200; AEC Grade: 0; AEC Qualified: Y; SizeArea_mm2: 1.28; SizeX_mm: 1.6; SizeY_mm: 0.8; SizeZ_mm: 1
R44 = CMP-0022532-4: RES, 60.4 k, 1%, 0.1 W, AEC-Q200 Grade 0, 0603; Manufacturer: Vishay-Dale; Value: 60.4k; Value_Code: 60k4; Power_W: 100mW; Value2: 0.1W; VDC_V: 75V; TempCo: 100 ppm/C; EIA_Code: E96; AEC Category: Q200; AEC Qualified: Y; AEC Grade: 0; SizeArea_mm2: 1.28; SizeX_mm: 1.6; SizeY_mm: 0.8; SizeZ_mm: 1
R46 = CMP-0022418-4: RES, 42.2 k, 1%, 0.1 W, AEC-Q200 Grade 0, 0603; PartNumber: CRCW060342K2FKEA; Manufacturer: Vishay-Dale; Value: 42.2k; Value_Code: 42k2; Power_W: 100mW; Value2: 0.1W; VDC_V: 75V; TempCo: 100 ppm/C; EIA_Code: E96; SizeArea_mm2: 1.28; SizeX_mm: 1.6; SizeY_mm: 0.8; SizeZ_mm: 1; AEC Category: Q200; AEC Qualified: Y; AEC Grade: 0
R47 = CMP-0022098-4: RES, 18.7 k, 1%, 0.1 W, AEC-Q200 Grade 0, 0603; PartNumber: CRCW060318K7FKEA; Manufacturer: Vishay-Dale; Value: 18.7k; Value_Code: 18k7; Power_W: 100mW; Value2: 0.1W; VDC_V: 75V; TempCo: 100 ppm/C; EIA_Code: E96; SizeArea_mm2: 1.28; SizeX_mm: 1.6; SizeY_mm: 0.8; SizeZ_mm: 1; AEC Category: Q200; AEC Qualified: Y; AEC Grade: 0
TP1 = CMP-0055121-1: Terminal, Turret, TH, Triple; PartNumber: 1598-2; Manufacturer: Keystone; CompType: Turret Terminal; Green_Lifecycle: Active; Green_REACh: Passed; CNHeader: FALSE
U6 = CMP-0013575-3: Multiphase Bidirectional Current Controller, PHP0048C (HTQFP-48); Manufacturer: Texas Instruments; Alternate PartNumber: LM5170QPHPTQ1; CompType: IC; SizeX_mm: 9; SizeZ_mm: 1.2; SizeArea_mm2: 81; SizeAreaWB_mm2: 121; AEC Category: Q200; AEC Qualified: Y; Rating: Automotive
U7 = CMP-0013548-2: 4A/6A Isolated Dual-Channel Gate Driver, NPL0013A (VLGA-13); Manufacturer: Texas Instruments; SizeX_mm: 5; CompType: IC; SizeZ_mm: 1; SizeArea_mm2: 25; SizeAreaWB_mm2: 49; U/M: EA

## Sheet PMP21943A-Power1.SchDoc: Power Stage
size 431 x 279 mm; Date: Not shown in title block; ApprovedBy: Not shown in title block; CheckedBy: Not shown in title block; Author: Not shown in title block; CompanyName: Not shown in title block; Engineer: Not shown in title block; Organization: Not shown in title block; Address1: Not shown in title block; Address2: Not shown in title block; Address3: Not shown in title block; Address4: Not shown in title block; DocumentNumber: 5; Revision: Use project parameter SCH_Rev; SheetNumber: 5; SheetTotal: 7; PageSetup: Record=PageOptions¦CenterHorizontal=True¦CenterVertical=True¦PrintScale=0.62¦XCorrection=1.00¦YCorrection=1.00¦PrintKind=0¦BorderSize=5000000¦LeftOffset=0¦BottomOffset=0¦Orientation=2¦PaperLength=1000¦PaperWidth=1000¦Scale=100¦PaperSource=15¦PrintQuality=600¦MediaType=1¦DitherType=10¦PrintScaleMode=1¦PaperKind=Letter (8.5 x 11")¦PaperIndex=1
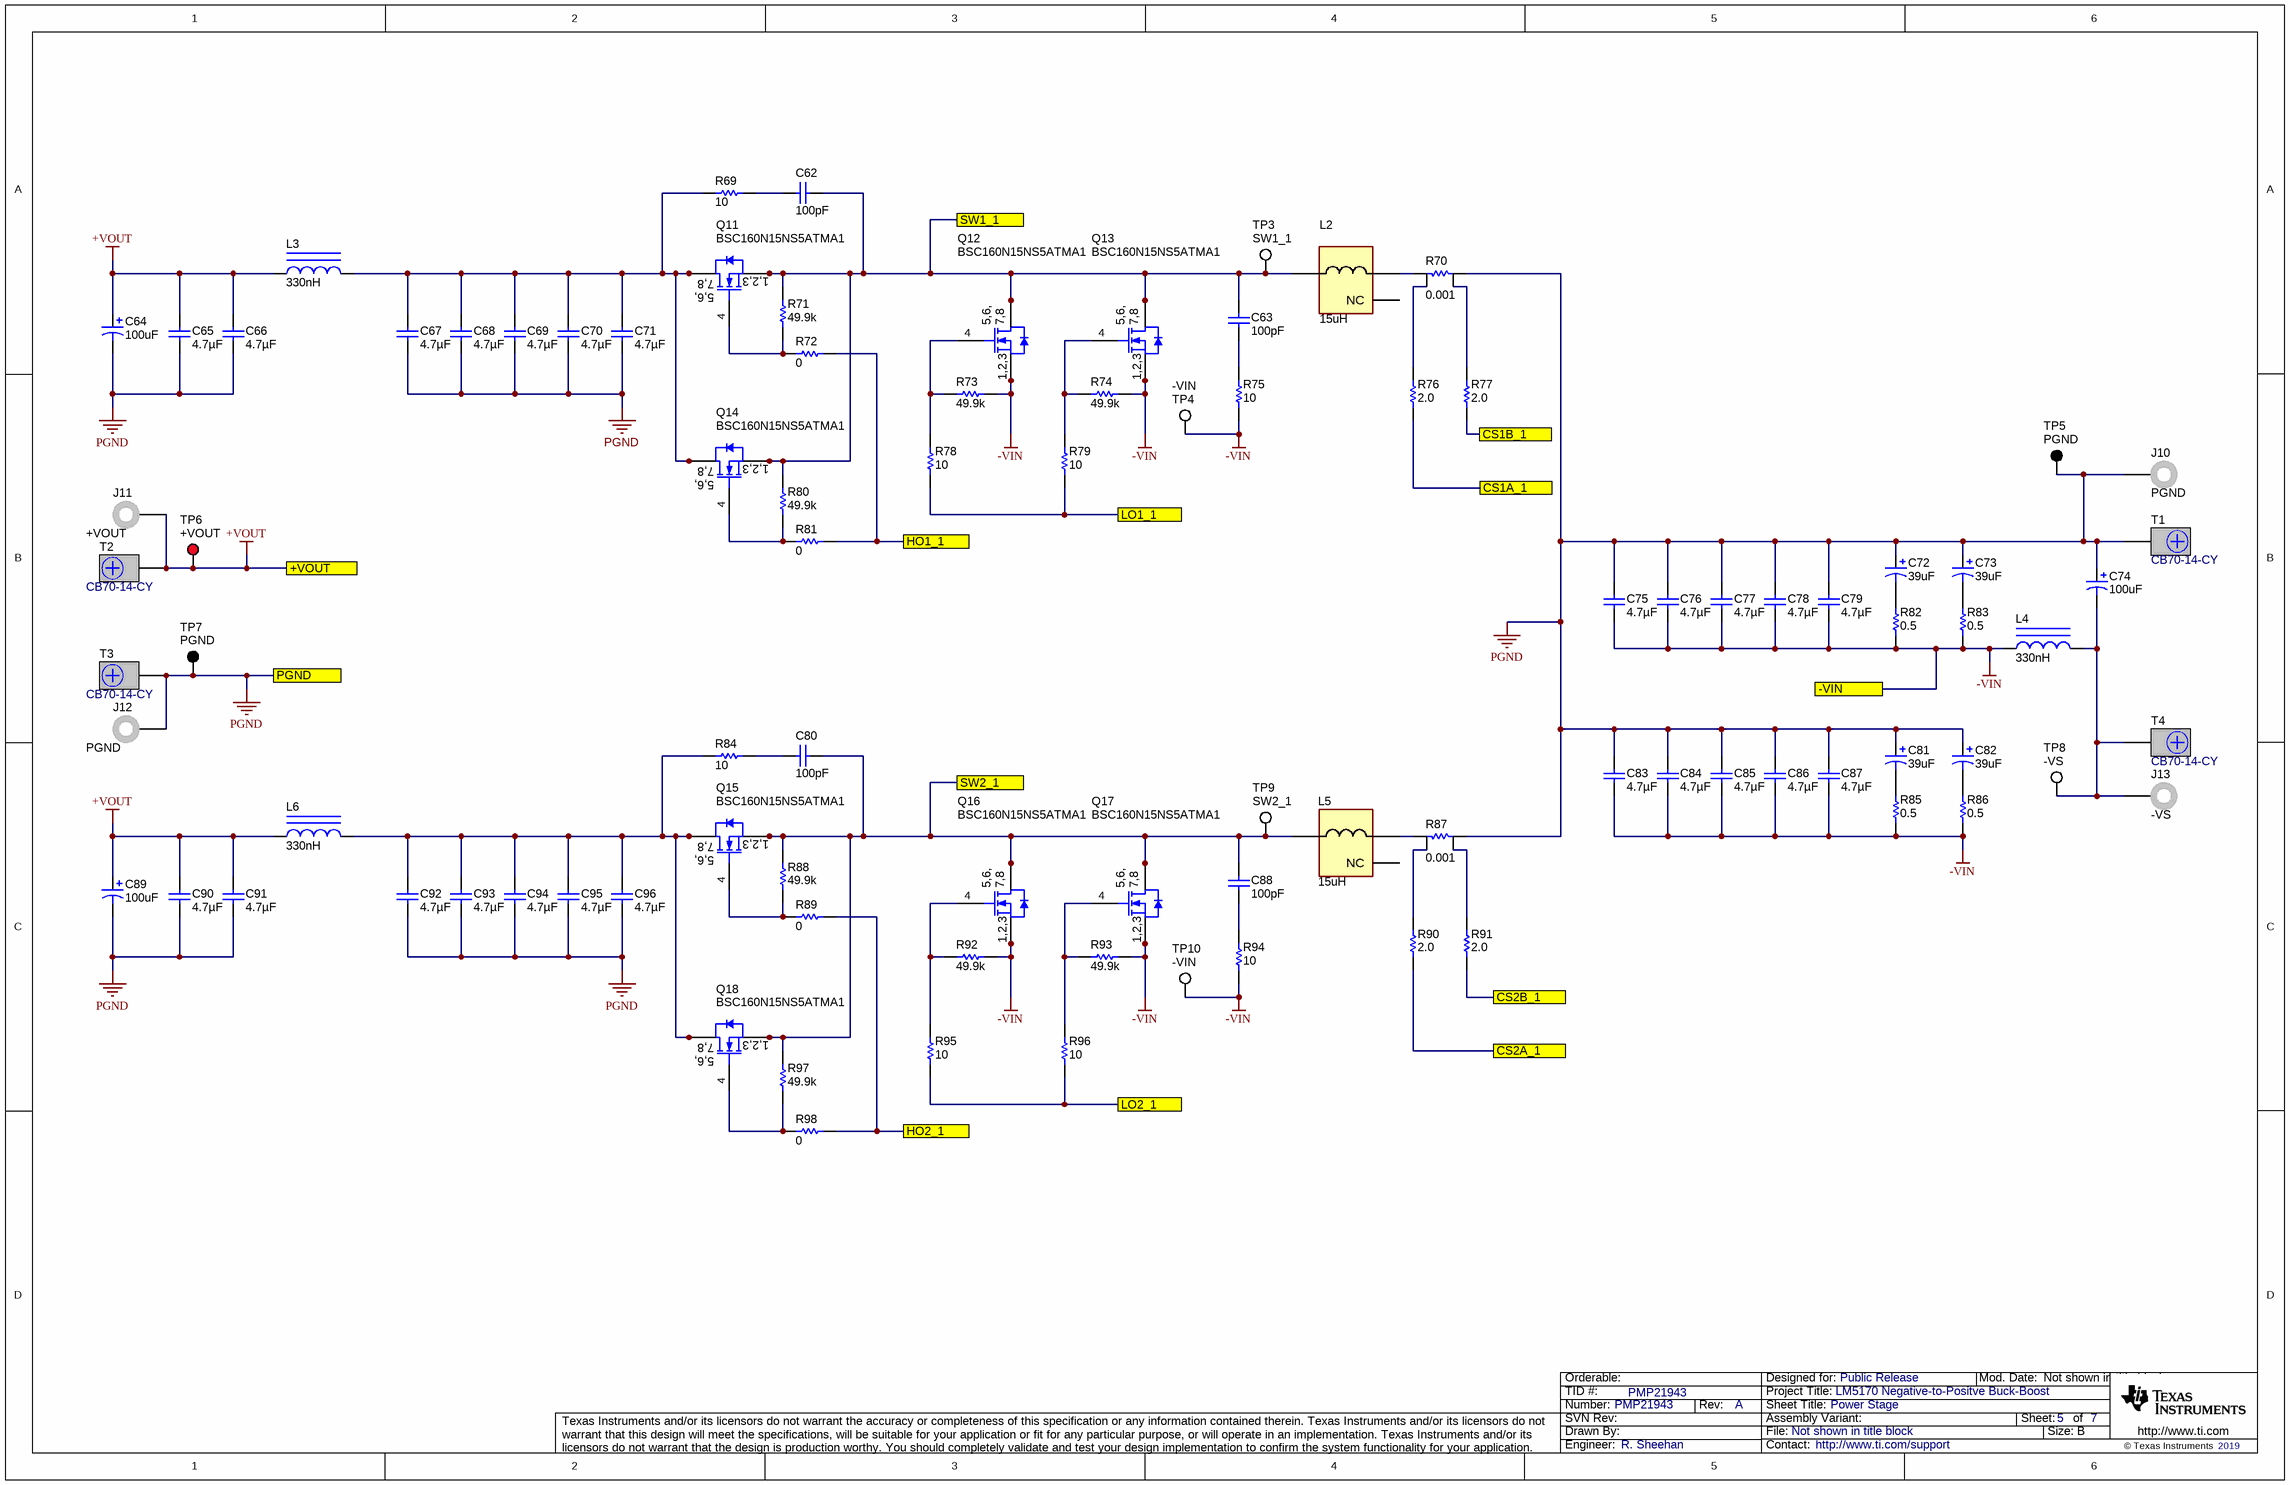
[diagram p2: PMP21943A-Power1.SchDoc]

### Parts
C62  ValueDisplayed: 100pF  [0805_HV]  (hidden comment: Capacitor)
C63  ValueDisplayed: 100pF  [0805_HV]  (hidden comment: Capacitor)
C64  ValueDisplayed: 100uF  [CR_1000x1270]  (hidden comment: Cap_Polarized)
C65  ValueDisplayed: 4.7µF  [1210_220L]  (hidden comment: GCM32DC72A475KE02L)
C66  ValueDisplayed: 4.7µF  [1210_220L]  (hidden comment: GCM32DC72A475KE02L)
C67  ValueDisplayed: 4.7µF  [1210_220L]  (hidden comment: GCM32DC72A475KE02L)
C68  ValueDisplayed: 4.7µF  [1210_220L]  (hidden comment: GCM32DC72A475KE02L)
C69  ValueDisplayed: 4.7µF  [1210_220L]  (hidden comment: GCM32DC72A475KE02L)
C70  ValueDisplayed: 4.7µF  [1210_220L]  (hidden comment: GCM32DC72A475KE02L)
C71  ValueDisplayed: 4.7µF  [1210_220L]  (hidden comment: GCM32DC72A475KE02L)
C72  ValueDisplayed: 39uF  [CR_800x1200]  (hidden comment: Cap_Polarized)
C73  ValueDisplayed: 39uF  [CR_800x1200]  (hidden comment: Cap_Polarized)
C74  ValueDisplayed: 100uF  [CAPSMT_62_LH0]  (hidden comment: Cap_Polarized)
C75  ValueDisplayed: 4.7µF  [1210_220L]  (hidden comment: GCM32DC72A475KE02L)
C76  ValueDisplayed: 4.7µF  [1210_220L]  (hidden comment: GCM32DC72A475KE02L)
C77  ValueDisplayed: 4.7µF  [1210_220L]  (hidden comment: GCM32DC72A475KE02L)
C78  ValueDisplayed: 4.7µF  [1210_220L]  (hidden comment: GCM32DC72A475KE02L)
C79  ValueDisplayed: 4.7µF  [1210_220L]  (hidden comment: GCM32DC72A475KE02L)
C80  ValueDisplayed: 100pF  [0805_HV]  (hidden comment: Capacitor)
C81  ValueDisplayed: 39uF  [CR_800x1200]  (hidden comment: Cap_Polarized)
C82  ValueDisplayed: 39uF  [CR_800x1200]  (hidden comment: Cap_Polarized)
C83  ValueDisplayed: 4.7µF  [1210_220L]  (hidden comment: GCM32DC72A475KE02L)
C84  ValueDisplayed: 4.7µF  [1210_220L]  (hidden comment: GCM32DC72A475KE02L)
C85  ValueDisplayed: 4.7µF  [1210_220L]  (hidden comment: GCM32DC72A475KE02L)
C86  ValueDisplayed: 4.7µF  [1210_220L]  (hidden comment: GCM32DC72A475KE02L)
C87  ValueDisplayed: 4.7µF  [1210_220L]  (hidden comment: GCM32DC72A475KE02L)
C88  ValueDisplayed: 100pF  [0805_HV]  (hidden comment: Capacitor)
C89  ValueDisplayed: 100uF  [CR_1000x1270]  (hidden comment: Cap_Polarized)
C90  ValueDisplayed: 4.7µF  [1210_220L]  (hidden comment: GCM32DC72A475KE02L)
C91  ValueDisplayed: 4.7µF  [1210_220L]  (hidden comment: GCM32DC72A475KE02L)
C92  ValueDisplayed: 4.7µF  [1210_220L]  (hidden comment: GCM32DC72A475KE02L)
C93  ValueDisplayed: 4.7µF  [1210_220L]  (hidden comment: GCM32DC72A475KE02L)
C94  ValueDisplayed: 4.7µF  [1210_220L]  (hidden comment: GCM32DC72A475KE02L)
C95  ValueDisplayed: 4.7µF  [1210_220L]  (hidden comment: GCM32DC72A475KE02L)
C96  ValueDisplayed: 4.7µF  [1210_220L]  (hidden comment: GCM32DC72A475KE02L)
J10  PGND  [Johnson_108-0740-001]
J11  +VOUT  [Johnson_108-0740-001]
J12  PGND  [Johnson_108-0740-001]
J13  -VS  [Johnson_108-0740-001]
L2  value 15uH  [FP-7443641500_SMT_IND_28MM0_19MM4-MFG]  (hidden comment: 7443641500)
L3  ValueDisplayed: 330nH  [VLBU1007090]  (hidden comment: VLBU1007090T-R33L)
L4  ValueDisplayed: 330nH  [VLBU1007090]  (hidden comment: VLBU1007090T-R33L)
L5  value 15uH  [FP-7443641500_SMT_IND_28MM0_19MM4-MFG]  (hidden comment: 7443641500)
L6  ValueDisplayed: 330nH  [VLBU1007090]  (hidden comment: VLBU1007090T-R33L)
Q11  BSC160N15NS5ATMA1  [PG-TDSON-8]
Q12  BSC160N15NS5ATMA1  [PG-TDSON-8]
Q13  BSC160N15NS5ATMA1  [PG-TDSON-8]
Q14  BSC160N15NS5ATMA1  [PG-TDSON-8]
Q15  BSC160N15NS5ATMA1  [PG-TDSON-8]
Q16  BSC160N15NS5ATMA1  [PG-TDSON-8]
Q17  BSC160N15NS5ATMA1  [PG-TDSON-8]
Q18  BSC160N15NS5ATMA1  [PG-TDSON-8]
R69  ValueDisplayed: 10  [2010]  (hidden comment: Resistor)
R70  ValueDisplayed: 0.001  [RES_WSL2726]  (hidden comment: Resistor_Kelvin)
R71  ValueDisplayed: 49.9k  [0603L]  (hidden comment: Resistor)
R72  ValueDisplayed: 0  [0603L]  (hidden comment: Resistor)
R73  ValueDisplayed: 49.9k  [0603L]  (hidden comment: Resistor)
R74  ValueDisplayed: 49.9k  [0603L]  (hidden comment: Resistor)
R75  ValueDisplayed: 10  [2010]  (hidden comment: Resistor)
R76  ValueDisplayed: 2.0  [0603L]  (hidden comment: Resistor)
R77  ValueDisplayed: 2.0  [0603L]  (hidden comment: Resistor)
R78  ValueDisplayed: 10  [0603L]  (hidden comment: CRCW060310R0JNEA)
R79  ValueDisplayed: 10  [0603L]  (hidden comment: CRCW060310R0JNEA)
R80  ValueDisplayed: 49.9k  [0603L]  (hidden comment: Resistor)
R81  ValueDisplayed: 0  [0603L]  (hidden comment: Resistor)
R82  ValueDisplayed: 0.5  [2010]  (hidden comment: Resistor)
R83  ValueDisplayed: 0.5  [2010]  (hidden comment: Resistor)
R84  ValueDisplayed: 10  [2010]  (hidden comment: Resistor)
R85  ValueDisplayed: 0.5  [2010]  (hidden comment: Resistor)
R86  ValueDisplayed: 0.5  [2010]  (hidden comment: Resistor)
R87  ValueDisplayed: 0.001  [RES_WSL2726]  (hidden comment: Resistor_Kelvin)
R88  ValueDisplayed: 49.9k  [0603L]  (hidden comment: Resistor)
R89  ValueDisplayed: 0  [0603L]  (hidden comment: Resistor)
R90  ValueDisplayed: 2.0  [0603L]  (hidden comment: Resistor)
R91  ValueDisplayed: 2.0  [0603L]  (hidden comment: Resistor)
R92  ValueDisplayed: 49.9k  [0603L]  (hidden comment: Resistor)
R93  ValueDisplayed: 49.9k  [0603L]  (hidden comment: Resistor)
R94  ValueDisplayed: 10  [2010]  (hidden comment: Resistor)
R95  ValueDisplayed: 10  [0603L]  (hidden comment: CRCW060310R0JNEA)
R96  ValueDisplayed: 10  [0603L]  (hidden comment: CRCW060310R0JNEA)
R97  ValueDisplayed: 49.9k  [0603L]  (hidden comment: Resistor)
R98  ValueDisplayed: 0  [0603L]  (hidden comment: Resistor)
T1  CB70-14-CY  [Panduit_CXS70-14-C]
T2  CB70-14-CY  [Panduit_CXS70-14-C]
T3  CB70-14-CY  [Panduit_CXS70-14-C]
T4  CB70-14-CY  [Panduit_CXS70-14-C]
TP3  SW1_1  [Testpoint_Keystone_Miniature]
TP4  -VIN  [Testpoint_Keystone_Miniature]
TP5  PGND  [Keystone5011]
TP6  +VOUT  [Keystone5010]
TP7  PGND  [Keystone5011]
TP8  -VS  [Keystone5012]
TP9  SW2_1  [Testpoint_Keystone_Miniature]
TP10  -VIN  [Testpoint_Keystone_Miniature]

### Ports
+VOUT, -VIN, CS1A_1, CS1B_1, CS2A_1, CS2B_1, HO1_1, HO2_1, LO1_1, LO2_1, PGND, SW1_1, SW2_1

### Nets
+VOUT: C64.1(+) C65.1 C66.1 C89.1(+) C90.1 C91.1 J11.1 L3.1 L6.1 T2.1 TP6.1 ; port +VOUT
-VIN: C75.2 C76.2 C77.2 C78.2 C79.2 C83.2 C84.2 C85.2 C86.2 C87.2 L4.1 Q12.1(S) Q12.2(S) Q12.3(S) Q13.1(S) Q13.2(S) Q13.3(S) Q16.1(S) Q16.2(S) Q16.3(S) Q17.1(S) Q17.2(S) Q17.3(S) R73.2 R74.2 R75.1 R82.1 R83.1 R85.1 R86.1 R92.2 R93.2 R94.1 TP4.1 TP10.1 ; port -VIN
PGND: C64.2(-) C65.2 C66.2 C67.2 C68.2 C69.2 C70.2 C71.2 C72.1(+) C73.1(+) C74.1(+) C75.1 C76.1 C77.1 C78.1 C79.1 C81.1(+) C82.1(+) C83.1 C84.1 C85.1 C86.1 C87.1 C89.2(-) C90.2 C91.2 C92.2 C93.2 C94.2 C95.2 C96.2 J10.1 J12.1 R70.2 R87.2 T1.1 T3.1 TP5.1 TP7.1 ; port PGND
CS1A_1: R76.1 ; port CS1A_1
CS1B_1: R77.1 ; port CS1B_1
CS2A_1: R90.1 ; port CS2A_1
CS2B_1: R91.1 ; port CS2B_1
HO1_1: R72.1 R81.1 ; port HO1_1
HO2_1: R89.1 R98.1 ; port HO2_1
LO1_1: R78.1 R79.1 ; port LO1_1
LO2_1: R95.1 R96.1 ; port LO2_1
SW1_1: C62.1 C63.1 L2.1 Q11.1(S) Q11.2(S) Q11.3(S) Q12.5(D) Q12.6(D) Q12.7(D) Q12.8(D) Q12.9(D) Q13.5(D) Q13.6(D) Q13.7(D) Q13.8(D) Q13.9(D) Q14.1(S) Q14.2(S) Q14.3(S) R71.1 R80.1 TP3.1 ; port SW1_1
SW2_1: C80.1 C88.1 L5.1 Q15.1(S) Q15.2(S) Q15.3(S) Q16.5(D) Q16.6(D) Q16.7(D) Q16.8(D) Q16.9(D) Q17.5(D) Q17.6(D) Q17.7(D) Q17.8(D) Q17.9(D) Q18.1(S) Q18.2(S) Q18.3(S) R88.2 R97.2 TP9.1 ; port SW2_1
NetC62_2: C62.2 R69.2
NetC63_2: C63.2 R75.2
NetC67_1: C67.1 C68.1 C69.1 C70.1 C71.1 L3.2 Q11.5(D) Q11.6(D) Q11.7(D) Q11.8(D) Q11.9(D) Q14.5(D) Q14.6(D) Q14.7(D) Q14.8(D) Q14.9(D) R69.1
NetC72_2: C72.2(-) R82.2
NetC73_2: C73.2(-) R83.2
NetC74_2: C74.2(-) J13.1 L4.2 T4.1 TP8.1
NetC80_2: C80.2 R84.2
NetC81_2: C81.2(-) R85.2
NetC82_2: C82.2(-) R86.2
NetC88_2: C88.2 R94.2
NetC92_1: C92.1 C93.1 C94.1 C95.1 C96.1 L6.2 Q15.5(D) Q15.6(D) Q15.7(D) Q15.8(D) Q15.9(D) Q18.5(D) Q18.6(D) Q18.7(D) Q18.8(D) Q18.9(D) R84.1
NetL2_2: L2.2 R70.1
NetL5_2: L5.2 R87.1
NetQ11_4: Q11.4(G) R71.2 R72.2
NetQ12_4: Q12.4(G) R73.1 R78.2
NetQ13_4: Q13.4(G) R74.1 R79.2
NetQ14_4: Q14.4(G) R80.2 R81.2
NetQ15_4: Q15.4(G) R88.1 R89.2
NetQ16_4: Q16.4(G) R92.1 R95.2
NetQ17_4: Q17.4(G) R93.1 R96.2
NetQ18_4: Q18.4(G) R97.1 R98.2
NetR70_3: R70.3 R76.2
NetR70_4: R70.4 R77.2
NetR87_3: R87.3 R90.2
NetR87_4: R87.4 R91.2

Not connected (* = marked no-connect by the designer): L2 3(NC); L5 3(NC)

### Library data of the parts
C62 C63 C80 C88 = CMP-0007518-2: CAP, CERM, 100 pF, 100 V, +/- 10%, C0G/NP0, 0805; PartNumber: 08051A101KAT2A; Manufacturer: AVX; Polarized: N; Value: 100pF; U/M: EA; ESR_ohm: 3.56d; Value1: 0.356 ohm; VDC_V: 100V; TaMin_C: -55°C; TaMax_C: 125°C; Cap_Case: 0805; AEC Category: Q200; SizeArea_mm2: 2.5; SizeAreaWB_mm2: 6.75; SizeX_mm: 2; SizeY_mm: 1.25; SizeZ_mm: 1.45
C64 C89 = CMP-0012274-3: CAP, Aluminum Polymer, 100 uF, 63 V, +/- 20%, 0.024 ohm, SMD, 2-Leads, Dia 10.5mm, Pin Spacing 8mm SMD; Manufacturer: Nichicon; PartNumber: PCR1J101MCL1GS; CompType: Capacitor; ESR_ohm: 0.024; VDC_V: 63V; Value: 100uF; Polarized: Y; Cap_F: 100µF; IRMS_A: 3A; TaMin_C: -55°C; TaMax_C: 125°C; Cap_Case: 10x12.7mm; AEC Category: Q200; AEC Qualified: N
C65 C66 C75 C83 C90 C91 = CMP-0082268-1: CAP, CERM, 4.7 µF, 100 V,+/- 10%, X7S, AEC-Q200 Grade 1, 1210; Manufacturer: MuRata; U/M: EA; ESR_ohm: 1m; VDC_V: 100V; Value: 4.7uF; Polarized: N; Value1: 0.001 ohm; IRMS_A: 6A; TaMin_C: -55°C; TaMax_C: 125°C; Cap_Case: 1210; AEC Category: Q200; AEC Qualified: Y; AEC Grade: 1; SizeArea_mm2: 8; SizeAreaWB_mm2: 14.7; SizeX_mm: 3.2; SizeY_mm: 2.5; SizeZ_mm: 2.2
C67-C71 C76-C79 C84-C87 C92-C96 = CMP-0082268-1: CAP, CERM, 4.7 µF, 100 V,+/- 10%, X7S, AEC-Q200 Grade 1, 1210; Manufacturer: MuRata; Polarized: N; Value: 4.7uF; U/M: EA; ESR_ohm: 1m; Value1: 0.001 ohm; VDC_V: 100V; IRMS_A: 6A; TaMin_C: -55°C; TaMax_C: 125°C; Cap_Case: 1210; AEC Category: Q200; AEC Qualified: Y; AEC Grade: 1; SizeArea_mm2: 8; SizeAreaWB_mm2: 14.7; SizeX_mm: 3.2; SizeY_mm: 2.5; SizeZ_mm: 2.2
C72 C73 C81 C82 = CMP-0012276-3: CAP, Aluminum Polymer, 39 uF, 80 V, +/- 20%, 0.035 ohm, D8xL12mm SMD; PartNumber: PCR1K390MCL1GS; Manufacturer: Nichicon; Polarized: Y; CompType: Capacitor; Value: 39uF; Cap_F: 39µF; VDC_V: 80V; ESR_ohm: 0.035; IRMS_A: 1.6A; TaMin_C: -55°C; TaMax_C: 125°C; Cap_Case: 8x12mm; AEC Category: Q200; AEC Qualified: N
C74 = CMP-0011313-2: CAP, AL, 100 uF, 100 V, +/- 20%, 0.24 ohm, SMD; PartNumber: EMVH101GDA101MLH0S; Manufacturer: Chemi-Con; Polarized: Y; CompType: Capacitor; Value: 100uF; U/M: EA; Cap_F: 100µF; VDC_V: 100V; ESR_ohm: 2.4d; IRMS_A: 6.5dA; TaMin_C: -40°C; TaMax_C: 125°C; Cap_Case: LH0; AEC Category: Q200; SizeArea_mm2: 289; SizeAreaWB_mm2: 361; SizeX_mm: 17; SizeZ_mm: 16.5
J10-J13 = CMP-0055387-2: Standard Banana Jack, Uninsulated, 15A; Manufacturer: Cinch Connectivity; CNHeader: FALSE; CT: TRUE; Green_Lifecycle: Active; Green_REACh: Passed
L2 L5 = CMP-0087002-1: Surface Mount Power Inductor, WE-HCF Series, 15 H, 15%, Shielded, 2400 ohm, 30 A; Manufacturer: Wurth Electronics; Imax_A: 30A; Isat: 26A; Material: Ferrite; SizeZ_mm: 18.5mm; AEC Qualified: No; Symbol Name: SYM-7443641500
L3 L4 L6 = CMP-0085710-1: Inductor, Shielded, Ferrite, 330 nH, 39 A, 0.000198 ohm, SMD; Manufacturer: TDK; Value: 330nH; Imax_A: 39A; Irms: 70A @ 40C rise; Isat: 39A @ 20% inductance drop; DCR_ohm: 198µ; SizeAreaWB_mm2: 108; SizeArea_mm2: 70; SizeX_mm: 10; SizeY_mm: 7; SizeZ_mm: 9; AEC Category: Q200; AEC Qualified: N
Q11-Q18 = CMP-0067566-1: MOSFET, N-CH, 150 V, 56 A, PG-TDSON-8; Manufacturer: Infineon Technologies; Alternate Manufacturer: None; U/M: EA; VdsMax_V: 150V; ChType: N; Value: 150V; Value1: ? ohm; Value2: 19 nC; QgTyp_nC: 19.0; Vgs_V: 20V; IdsMax_A: 56A; SizeAreaWB_mm2: 55.131; SizeArea_mm2: 29.351; SizeX_mm: 5.99; SizeY_mm: 4.9; SizeZ_mm: 1.12; AEC Category: Q101
R69 R75 R84 R94 = CMP-0016049-3: RES, 10, 5%, 0.75 W, AEC-Q200 Grade 0, 2010; PartNumber: CRCW201010R0JNEF; Manufacturer: Vishay-Dale; Value: 10; Value_Code: 10R0; Power_W: 750mW; Value2: 0.75W; VDC_V: 400V; TempCo: 200 ppm/C; EIA_Code: E24; SizeArea_mm2: 12.5; SizeX_mm: 5; SizeY_mm: 2.5; SizeZ_mm: 1.66; AEC Category: Q200; AEC Qualified: Y; AEC Grade: 0
R70 R87 = CMP-0015287-2: RES, 0.001, 1%, 3 W, 6.6x3x6.9mm; Manufacturer: Vishay-Dale; PartNumber: WSL27261L000FEB; U/M: EA; Value: 0.001; TempCo: 75 ppm/C; Power_W: 3W; Res_ohm: 1m; Value_Code: 1L000; EIA_Code: E96; AEC Category: Q200
R71 R73 R74 R80 R88 R92 R93 R97 = CMP-0022447-4: RES, 49.9 k, 1%, 0.1 W, AEC-Q200 Grade 0, 0603; PartNumber: CRCW060349K9FKEA; Manufacturer: Vishay-Dale; Value: 49.9k; Value_Code: 49k9; Power_W: 100mW; Value2: 0.1W; VDC_V: 75V; TempCo: 100 ppm/C; EIA_Code: E96; SizeArea_mm2: 1.28; SizeX_mm: 1.6; SizeY_mm: 0.8; SizeZ_mm: 1; AEC Category: Q200; AEC Qualified: Y; AEC Grade: 0
R72 R81 R89 R98 = CMP-0025697-4: RES, 0, 5%, 0.1 W, AEC-Q200 Grade 0, 0603; PartNumber: CRCW06030000Z0EA; Manufacturer: Vishay-Dale; Value: 0; Value_Code: 0000; Power_W: 100mW; Value2: 0.1W; VDC_V: 75V; TempCo: 200 ppm/C; EIA_Code: E24; SizeArea_mm2: 1.28; SizeX_mm: 1.6; SizeY_mm: 0.8; SizeZ_mm: 1; AEC Category: Q200; AEC Qualified: Y
R76 R77 R90 R91 = CMP-0025776-4: as R38 on sheet PMP21943A-Controller1
R78 R79 R95 R96 = CMP-0025703-4: RES, 10, 5%, 0.1 W, AEC-Q200 Grade 0, 0603; Manufacturer: Vishay-Dale; Value: 10; Value_Code: 10R0; Power_W: 100mW; Value2: 0.1W; VDC_V: 75V; TempCo: 200 ppm/C; EIA_Code: E24; SizeArea_mm2: 1.28; SizeX_mm: 1.6; SizeY_mm: 0.8; SizeZ_mm: 1; AEC Category: Q200; AEC Qualified: Y; AEC Grade: 0
R82 R83 R85 R86 = CMP-0016530-2: RES, 0.5, 1%, 1 W, 2010; PartNumber: CSRN2010FKR500; Manufacturer: Stackpole Electronics Inc; Value: 0.5; Res_ohm: 5d; Value_Code: R500; Power_W: 1W; TempCo: 250 ppm/C; U/M: EA; SizeArea_mm2: 12.5; SizeX_mm: 5; SizeY_mm: 2.5; SizeZ_mm: 1.66; AEC Category: Q200
T1-T4 = CMP-0075010-1: Terminal 70A Lug; PartNumber: CXS70-14-C; Manufacturer: Panduit; CompType: Screw Terminal; CNHeader: False; Green_Lifecycle: Not Set; Green_REACh: Incomplete
TP3 TP4 TP9 TP10 = CMP-0055152-1: Test Point, Miniature, SMT; Manufacturer: Keystone; Green_Lifecycle: Active; Green_REACh: Passed; CNHeader: FALSE; CT: TRUE
TP5 TP7 = CMP-0055148-1: Test Point, Multipurpose, Black, TH; Manufacturer: Keystone; ContactFinish: Silver; Green_Lifecycle: Active; Green_REACh: Passed; CNHeader: FALSE; CT: TRUE
TP6 = CMP-0055147-1: Test Point, Multipurpose, Red, TH; Manufacturer: Keystone; ContactFinish: Silver; Green_Lifecycle: Active; Green_REACh: Passed; CNHeader: FALSE; CT: TRUE
TP8 = CMP-0055149-1: Test Point, Multipurpose, White, TH; Manufacturer: Keystone; ContactFinish: Silver; Green_Lifecycle: Active; Green_REACh: Passed; CNHeader: FALSE; CT: TRUE

## Sheet PMP21943A-HW.SchDoc: Hardware
size 431 x 279 mm; Date: Not shown in title block; ApprovedBy: Not shown in title block; CheckedBy: Not shown in title block; Author: Not shown in title block; CompanyName: Not shown in title block; Engineer: Not shown in title block; Organization: Not shown in title block; Address1: Not shown in title block; Address2: Not shown in title block; Address3: Not shown in title block; Address4: Not shown in title block; DocumentNumber: 7; Revision: Use project parameter SCH_Rev; SheetNumber: 7; SheetTotal: 7; PageSetup: Record=PageOptions¦CenterHorizontal=True¦CenterVertical=True¦PrintScale=1.00¦XCorrection=1.00¦YCorrection=1.00¦PrintKind=0¦BorderSize=5000000¦LeftOffset=0¦BottomOffset=0¦Orientation=2¦PaperLength=1000¦PaperWidth=1000¦Scale=100¦PaperSource=15¦PrintQuality=600¦MediaType=1¦DitherType=10¦PaperKind=Letter¦PrintScaleMode=1
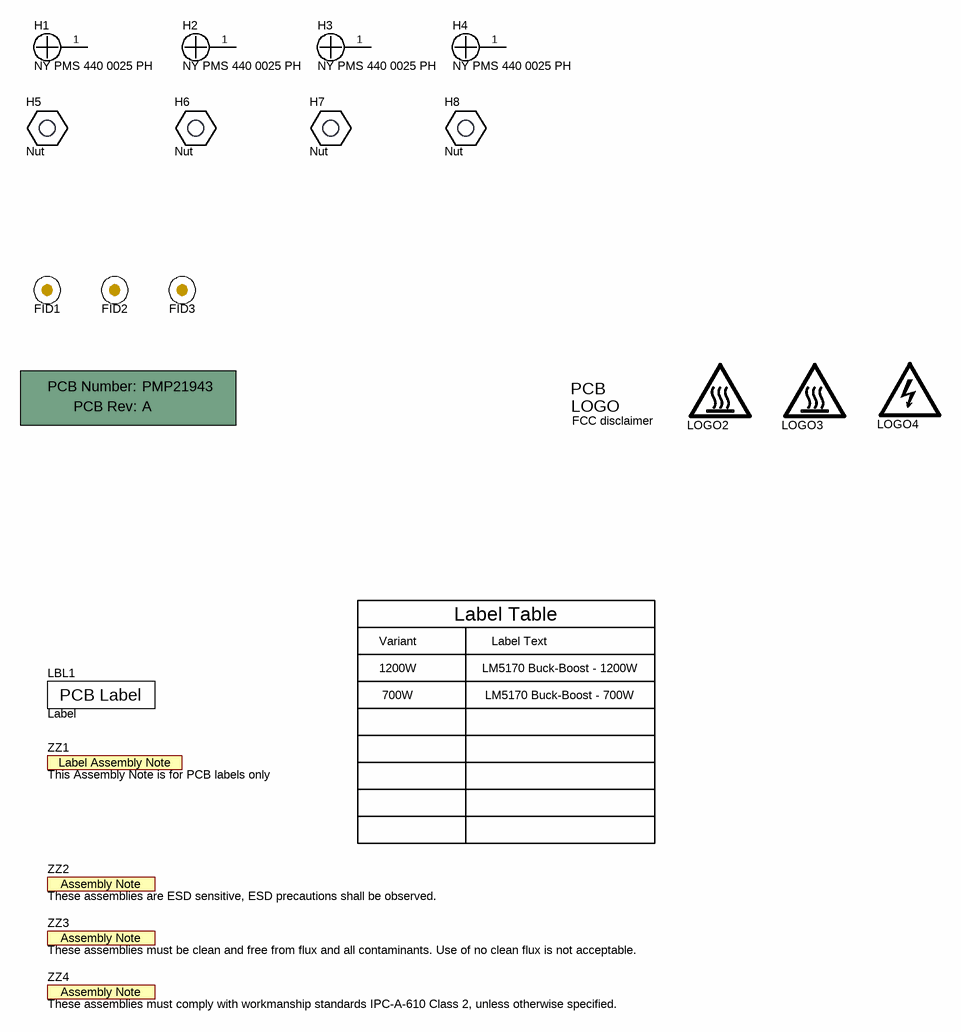
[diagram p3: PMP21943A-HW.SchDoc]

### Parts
!PCB1  Printed Circuit Board  (value not drawn)  (mechanical)
FID1  Fiducial  [Fiducial10-20]  (value not drawn)
FID2  Fiducial  [Fiducial10-20]  (value not drawn)
FID3  Fiducial  [Fiducial10-20]  (value not drawn)
H1  NY PMS 440 0025 PH  [NY PMS 440 0025 PH]
H2  NY PMS 440 0025 PH  [NY PMS 440 0025 PH]
H3  NY PMS 440 0025 PH  [NY PMS 440 0025 PH]
H4  NY PMS 440 0025 PH  [NY PMS 440 0025 PH]
H5  Nut  [KEYSTONE_2205]
H6  Nut  [KEYSTONE_2205]
H7  Nut  [KEYSTONE_2205]
H8  Nut  [KEYSTONE_2205]
LBL1  Label  [Label_1250x250]
Logo1  FCC disclaimer  [FCC_disclaimer_stacked]  (no BOM)
LOGO2  CAUTION HOT SURFACE  [IEC_HotSurface_Small]  (value not drawn)  (no BOM)
LOGO3  CAUTION HOT SURFACE  [IEC_HotSurface_Small]  (value not drawn)  (no BOM)
LOGO4  DANGER HIGH VOLTAGE  [IEC_HighVoltage_Small]  (value not drawn)  (no BOM)
ZZ1  This Assembly Note is for PCB labels only  [AssemblyNoteLabel]  (no BOM)
ZZ2  These assemblies are ESD sensitive, ESD precautions shall be observed.  [AssemblyNote]  (no BOM)
ZZ3  These assemblies must be clean and free from flux and all contaminants. Use of no clean flux is not acceptable.  [AssemblyNote]  (no BOM)
ZZ4  These assemblies must comply with workmanship standards IPC-A-610 Class 2, unless otherwise specified.  [AssemblyNote]  (no BOM)

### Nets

Not connected (* = marked no-connect by the designer): H1 1; H2 1; H3 1; H4 1

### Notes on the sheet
- Variant
- Label Table
- Label Text
- 1200W
- 700W
- LM5170 Buck-Boost - 1200W
- LM5170 Buck-Boost - 700W

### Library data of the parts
!PCB1 = CMP-0003618-2: Manufacturer: Any; PartNumber: PMP21943
FID1-FID3 = CMP-0077181-1: Fiducial mark.  There is nothing to buy or mount.
H1-H4 = CMP-0003617-1: Machine Screw, Round, #4-40 x 1/4, Nylon, Philips panhead; Manufacturer: B&F Fastener Supply; CompType: Hardware
H5-H8 = CMP-0003655-1: Standoff, Hex, 1"L #4-40 Aluminum; Manufacturer: Keystone; PartNumber: 2205
LBL1 = CMP-0003624-1: Thermal Transfer Printable Labels, 1.250" W x 0.250" H - 10,000 per roll; Manufacturer: Brady; PartNumber: THT-13-457-10; Note: Size: 1.25" x 0.25"
Logo1 = CMP-0074847-1: FCC_disclaimer
LOGO2 LOGO3 = CMP-0074837-1: IEC 61010-1 Hot Surface Warning; SymbolCreator: a0412235
LOGO4 = CMP-0074835-1: IEC 61010-1 High Voltage Warning; SymbolCreator: a0412235
ZZ1 = CMP-0003616-3
ZZ2 = CMP-0077236-1
ZZ3 = CMP-0077237-1
ZZ4 = CMP-0077238-1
